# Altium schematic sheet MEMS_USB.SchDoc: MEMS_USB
size A4; DocumentNumber: 6; Revision: D01(PCB.SCH); SheetNumber: 4; SheetTotal: 6
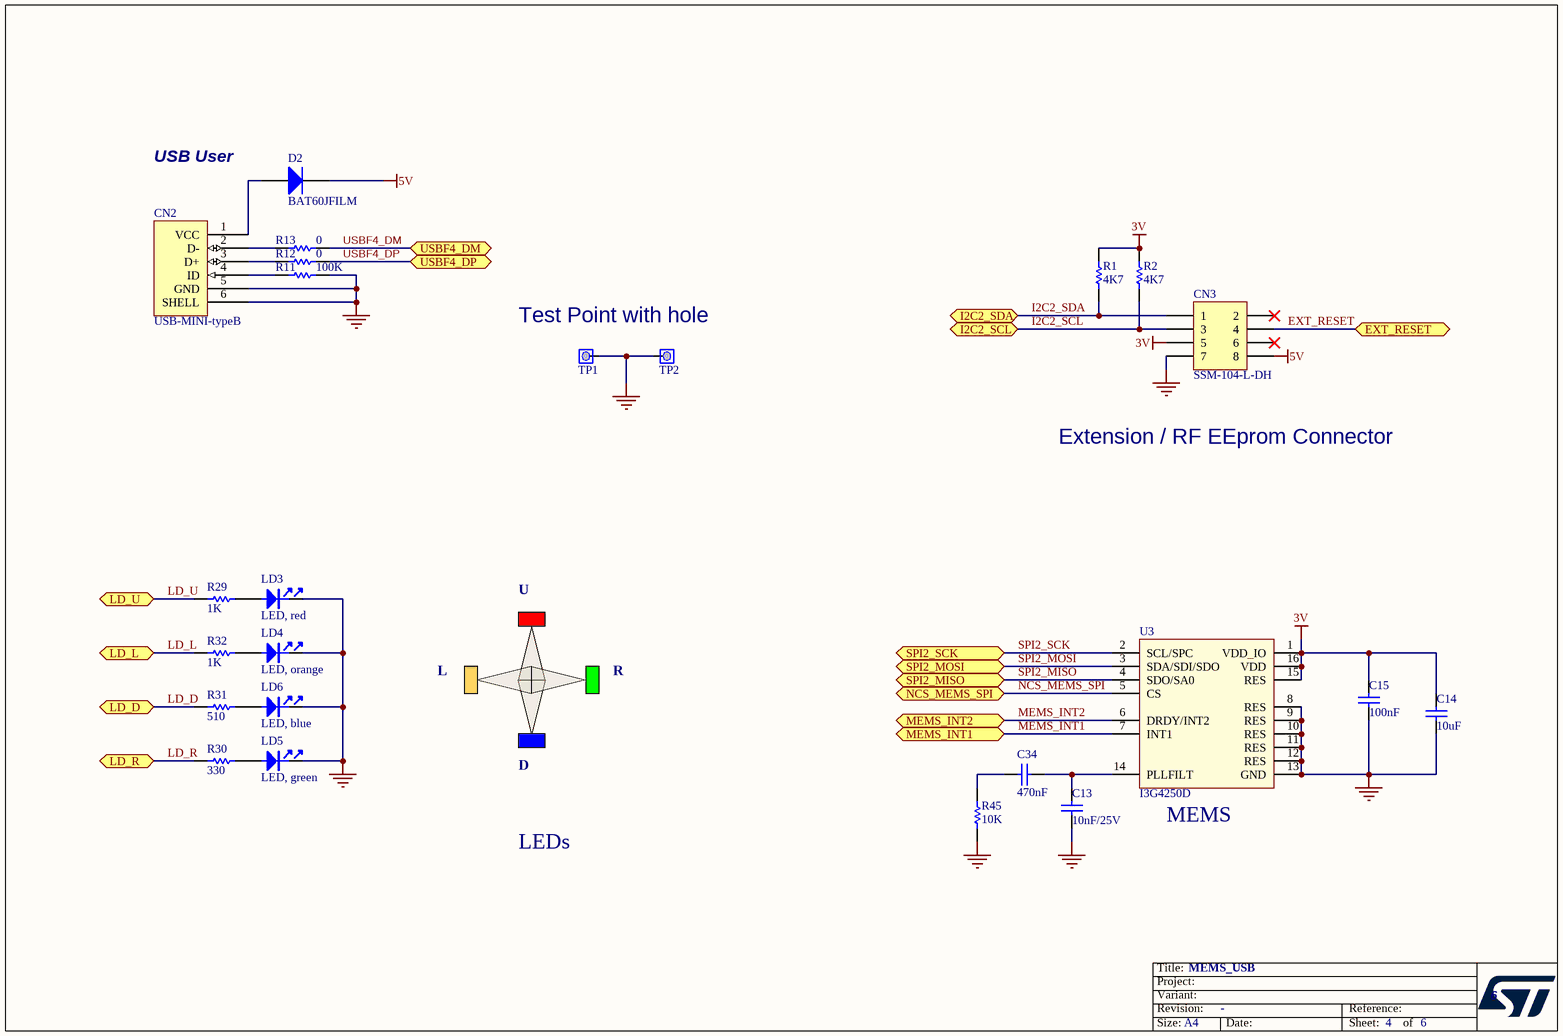
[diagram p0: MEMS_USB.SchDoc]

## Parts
C13  10nF/25V  [0603C]
C14  10uF  [0603C]
C15  100nF  [0402C]
C34  value 470nF  [C0603]  (hidden comment: Capacitor)
CN2  USB-MINI-typeB  [USB-MINI-B-SMD]
CN3  SSM-104-L-DH  [SSM-104-L-DH]
D2  BAT60JFILM  [SOD323/A]
LD3  LED, red  [0603D]
LD4  LED, orange  [0603D]
LD5  LED, green  [0603D]
LD6  LED, blue  [0603D]
R1  4K7  [0402R]
R2  4K7  [0402R]
R11  100K  [0402R]
R12  0  [0402R]
R13  0  [0402R]
R29  1K  [0603R]
R30  330  [0603R]
R31  510  [0603R]
R32  1K  [0603R]
R45  10K  [0402R]
TP1  Test point 1 pin with hole  [SIP1/2.54]  (value not drawn)
TP2  Test point 1 pin with hole  [SIP1/2.54]  (value not drawn)
U3  I3G4250D  [ICC_LGA16_4X4_P065_H1P1]

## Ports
EXT_RESET, I2C2_SCL, I2C2_SDA, LD_D, LD_L, LD_R, LD_U, MEMS_INT1, MEMS_INT2, NCS_MEMS_SPI, SPI2_MISO, SPI2_MOSI, SPI2_SCK, USBF4_DM, USBF4_DP

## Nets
3V: C14.2 C15.2 CN3.5 R1.2 R2.2 U3.1(VDD_IO) U3.15(RES) U3.16(VDD)
5V: CN3.8 D2.2(K)
GND: C13.1 C14.1 C15.1 CN2.5(GND) CN2.6(SHELL) CN3.7 LD3.2 LD4.2 LD5.2 LD6.2 R11.2 R45.1 TP1.1(COMMON) TP2.1(COMMON) U3.8(RES) U3.9(RES) U3.10(RES) U3.11(RES) U3.12(RES) U3.13(GND)
EXT_RESET: CN3.4 ; port EXT_RESET
I2C2_SCL: CN3.3 R2.1 ; port I2C2_SCL
I2C2_SDA: CN3.1 R1.1 ; port I2C2_SDA
LD_D: R31.1 ; port LD_D
LD_L: R32.1 ; port LD_L
LD_R: R30.1 ; port LD_R
LD_U: R29.1 ; port LD_U
MEMS_INT1: U3.7(INT1) ; port MEMS_INT1
MEMS_INT2: U3.6(DRDY/INT2) ; port MEMS_INT2
NCS_MEMS_SPI: U3.5(CS) ; port NCS_MEMS_SPI
SPI2_MISO: U3.4(SDO/SA0) ; port SPI2_MISO
SPI2_MOSI: U3.3(SDA/SDI/SDO) ; port SPI2_MOSI
SPI2_SCK: U3.2(SCL/SPC) ; port SPI2_SCK
USBF4_DM: R13.2 ; port USBF4_DM
USBF4_DP: R12.2 ; port USBF4_DP
NetC13_2: C13.2 C34.1 U3.14(PLLFILT)
NetC34_2: C34.2 R45.2
NetCN2_1: CN2.1(VCC) D2.1(A)
NetCN2_2: CN2.2(D-) R13.1
NetCN2_3: CN2.3(D+) R12.1
NetCN2_4: CN2.4(ID) R11.1
NetLD3_1: LD3.1 R29.2
NetLD4_1: LD4.1 R32.2
NetLD5_1: LD5.1 R30.2
NetLD6_1: LD6.1 R31.2

Not connected (* = marked no-connect by the designer): CN3 2* 6*

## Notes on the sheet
- USB User
- Test Point with hole
- Extension / RF EEprom Connector
- U
- L
- R
- D
- LEDs
- (near U3) MEMS

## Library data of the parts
C13 C14 = CAP: Capacitor; Value: 100nF
C15 = Capacitor_ST: Capacitor 0402 / 0603 / 0805
C34 = MCD-01006: Capacitor, MLCC, 470nF, 16V, X7R, 10%, 0603, T=0.8mm; Manufacturer_Part_Number: CC0603KRX7R7BB474; Manufacturer: YAGEO; BMS_Part_Number: 9142003; Provided_By: SUBCO
CN2 = USB-MINI-typeB connector: Manuf_Part_1: 5075BMR-05-SM
CN3 = SSM-104-L-DH: Header, 5-Pin, Dual row
D2 = BAT60JFILM: Manuf_1: STM; Provided: ST; ECCN_US/EU: EAR99/NEC
LD3 = LED_red: LED, red, 0603; Manuf_1: everlight; Manuf_Part_1: 19-213-R6C-AP1Q2B/3T
LD4 = LED_orange: LED, orange, 0603; Manuf_1: everlight; Manuf_Part_1: 19-217/S2C-AM2N2VY/3T
LD5 = LED_green: LED, green, 0603; Manuf_1: everlight; Manuf_Part_1: 19-213SYGC/S530-E2/TR8
LD6 = LED_blue: LED, blue, 0603; Manuf_1: everlight; Manuf_Part_1: 19-217/BHC-ZL1M2RY/3T
R1 R2 R11-R13 R29-R32 = Resistor_ST: Resistor 0402 / 0603 / 0805; Value: 10K
R45 = Resistor_ST: Resistor 0402 / 0603 / 0805
TP1 TP2 = TP1: Test Point; Fitted: NO
U3 = MCD-01963: MEMS motion sensor: 3-axis digital output gyroscope LG4-16 4x4mm; Part_Type: IC; Manufacturer: STMICROELECTRONICS; ECCN_US: EAR99; ECCN_EU: NEC; Provided_By: SUBCO with ST control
